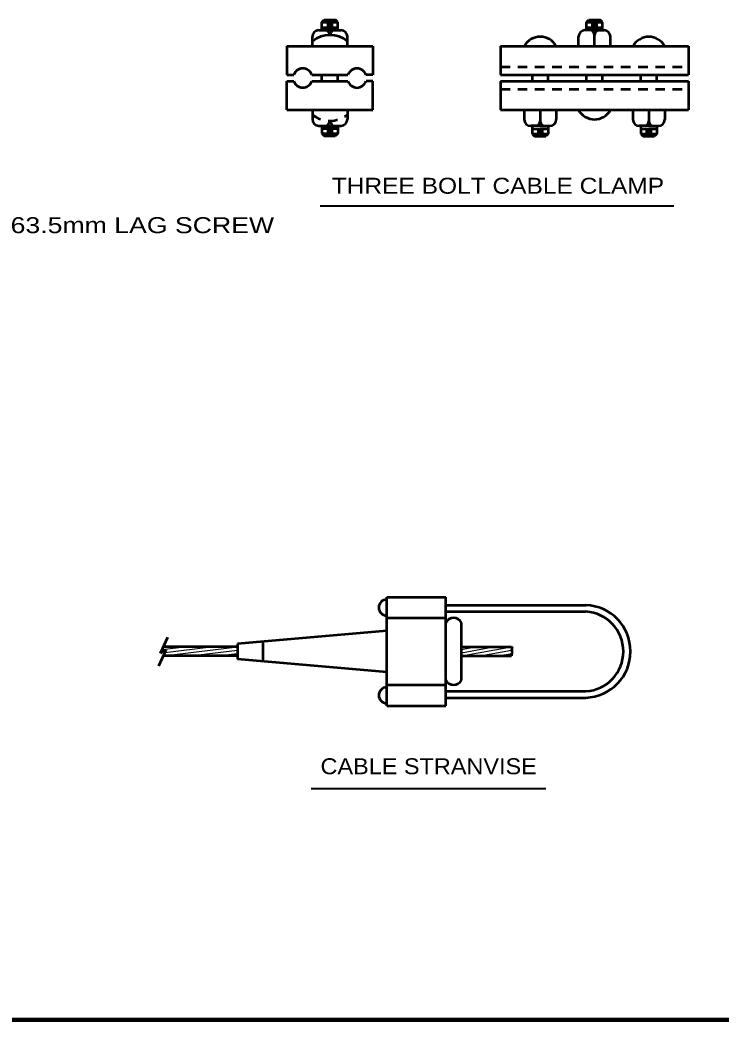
# Model space of a CAD drawing. Extents: x 14808 to 15663, y 10944 to 11488.
# Drawn here: x 15163.9 to 15295.9, y 10955.6 to 11143.7 of the extents above; entities that cross this region are included whole.
import ezdxf
from ezdxf.enums import TextEntityAlignment as Align

# ---------------------------------------------------------------- set-up
doc = ezdxf.new("R2010")
doc.units = 0
doc.header["$LTSCALE"] = 1.2
doc.linetypes.add('SHORT_DASHED', pattern=[2.7, 1.5, -1.2])
doc.layers.add('1', color=7, linetype='Continuous', lineweight=53)

msp = doc.modelspace()

# ---------------------------------------------------------------- linework, layer by layer
at = {"layer": '1'}
for p, q in [((15220.789, 11143.284), (15221.213, 11143.708)), ((15220.789, 11143.284), (15223.789, 11143.284)), ((15220.789, 11141.784), (15220.789, 11143.284)), ((15221.213, 11143.708), (15223.364, 11143.708)), ((15223.789, 11143.284), (15223.364, 11143.708)), ((15223.789, 11141.784), (15223.789, 11143.284)), ((15270.588, 11143.284), (15271.013, 11143.708)), ((15270.588, 11141.784), (15270.588, 11143.284)), ((15270.588, 11143.284), (15273.588, 11143.284)), ((15271.013, 11143.708), (15273.164, 11143.708)), ((15273.588, 11143.284), (15273.164, 11143.708)), ((15273.588, 11141.784), (15273.588, 11143.284)), ((15220.189, 11141.784), (15224.389, 11141.784)), ((15220.789, 11142.324), (15223.789, 11142.324)), ((15221.689, 11142.804), (15222.889, 11142.804)), ((15272.088, 11141.784), (15270.289, 11141.784)), ((15270.588, 11142.324), (15273.588, 11142.324)), ((15271.489, 11142.804), (15272.689, 11142.804)), ((15272.088, 11141.784), (15273.889, 11141.784)), ((15218.989, 11138.784), (15218.989, 11140.584)), ((15225.588, 11138.784), (15225.588, 11140.584)), ((15269.088, 11138.784), (15269.088, 11140.584)), ((15272.088, 11138.784), (15272.088, 11140.884)), ((15275.088, 11138.784), (15275.088, 11140.584)), ((15214.189, 11138.784), (15230.389, 11138.784)), ((15214.189, 11138.784), (15214.189, 11133.384)), ((15230.389, 11138.784), (15230.389, 11133.384)), ((15254.389, 11138.784), (15289.789, 11138.784)), ((15254.389, 11138.784), (15254.389, 11133.384)), ((15289.789, 11138.784), (15289.789, 11133.384)), ((15214.189, 11133.384), (15215.486, 11133.384)), ((15214.189, 11126.784), (15214.189, 11132.184)), ((15214.189, 11132.184), (15215.486, 11132.184)), ((15218.88, 11133.384), (15225.684, 11133.384)), ((15218.88, 11132.184), (15225.681, 11132.184)), ((15220.789, 11132.184), (15220.789, 11133.384)), ((15223.789, 11132.184), (15223.789, 11133.384)), ((15230.389, 11133.384), (15229.075, 11133.384)), ((15230.389, 11132.184), (15229.078, 11132.184)), ((15230.389, 11126.784), (15230.389, 11132.184)), ((15254.389, 11133.384), (15289.789, 11133.384)), ((15254.389, 11132.184), (15254.389, 11126.784)), ((15260.389, 11132.184), (15260.389, 11133.384)), ((15263.389, 11132.184), (15263.389, 11133.384)), ((15270.588, 11132.184), (15270.588, 11133.384)), ((15273.588, 11132.184), (15273.588, 11133.384)), ((15280.789, 11132.184), (15280.789, 11133.384)), ((15283.789, 11132.184), (15283.789, 11133.384)), ((15289.789, 11132.184), (15289.789, 11126.784)), ((15214.189, 11126.784), (15230.389, 11126.784)), ((15218.989, 11126.833), (15218.989, 11125.033)), ((15225.588, 11126.833), (15225.588, 11125.033)), ((15254.389, 11126.784), (15289.789, 11126.784)), ((15258.872, 11126.792), (15258.872, 11124.992)), ((15261.872, 11126.792), (15261.872, 11124.692)), ((15264.872, 11126.792), (15264.872, 11124.992)), ((15279.311, 11126.779), (15279.311, 11124.979)), ((15282.311, 11126.779), (15282.311, 11124.679)), ((15285.311, 11126.779), (15285.311, 11124.979)), ((15220.189, 11123.833), (15224.389, 11123.833)), ((15220.789, 11123.833), (15220.789, 11122.333)), ((15220.789, 11123.293), (15223.789, 11123.293)), ((15221.689, 11122.813), (15222.889, 11122.813)), ((15223.789, 11123.833), (15223.789, 11122.333)), ((15261.872, 11123.792), (15260.072, 11123.792)), ((15260.372, 11123.792), (15260.372, 11122.292)), ((15260.372, 11123.252), (15263.372, 11123.252)), ((15261.272, 11122.772), (15262.472, 11122.772)), ((15261.872, 11123.792), (15263.672, 11123.792)), ((15263.372, 11123.792), (15263.372, 11122.292)), ((15282.311, 11123.779), (15280.511, 11123.779)), ((15280.811, 11123.779), (15280.811, 11122.279)), ((15280.811, 11123.239), (15283.811, 11123.239)), ((15281.711, 11122.759), (15282.911, 11122.759)), ((15282.311, 11123.779), (15284.111, 11123.779)), ((15283.811, 11123.779), (15283.811, 11122.279)), ((15220.789, 11122.333), (15221.213, 11121.909)), ((15220.789, 11122.333), (15223.789, 11122.333)), ((15221.213, 11121.909), (15223.364, 11121.909)), ((15223.789, 11122.333), (15223.364, 11121.909)), ((15260.372, 11122.292), (15260.796, 11121.868)), ((15260.372, 11122.292), (15263.372, 11122.292)), ((15260.796, 11121.868), (15262.948, 11121.868)), ((15263.372, 11122.292), (15262.948, 11121.868)), ((15280.811, 11122.279), (15281.235, 11121.855)), ((15280.811, 11122.279), (15283.811, 11122.279)), ((15281.235, 11121.855), (15283.387, 11121.855)), ((15283.811, 11122.279), (15283.387, 11121.855)), ((15232.974, 11035.153), (15244.074, 11035.153)), ((15232.974, 11031.253), (15232.974, 11035.153)), ((15244.074, 11014.753), (15244.074, 11035.153)), ((15244.074, 11033.653), (15270.474, 11033.653)), ((15244.074, 11032.453), (15270.474, 11032.453)), ((15232.974, 11031.253), (15244.074, 11031.253)), ((15247.074, 11019.553), (15247.074, 11030.353)), ((15232.974, 11028.853), (15204.882, 11026.395)), ((15190.411, 11024.637), (15191.805, 11027.627)), ((15209.682, 11026.815), (15209.682, 11023.091)), ((15190.099, 11022.257), (15191.494, 11025.248)), ((15190.411, 11024.637), (15191.494, 11025.248)), ((15204.882, 11025.795), (15190.951, 11025.795)), ((15204.882, 11026.395), (15204.882, 11023.511)), ((15247.074, 11025.795), (15256.482, 11025.795)), ((15204.882, 11024.111), (15190.963, 11024.111)), ((15232.974, 11021.053), (15204.882, 11023.511)), ((15247.074, 11024.111), (15256.482, 11024.111)), ((15232.974, 11018.653), (15244.074, 11018.653)), ((15244.074, 11017.453), (15270.474, 11017.453)), ((15244.074, 11016.253), (15270.474, 11016.253)), ((15232.974, 11014.753), (15244.074, 11014.753))]:
    msp.add_line(p, q, dxfattribs=at)
at = {"layer": '1', "linetype": 'SHORT_DASHED'}
for p, q in [((15254.389, 11134.884), (15289.789, 11134.884)), ((15254.389, 11130.684), (15289.789, 11130.684))]:
    msp.add_line(p, q, dxfattribs=at)
at = {"layer": '1', "lineweight": 13}
msp.add_line((15218.889, 11133.384), (15218.989, 11133.384), dxfattribs=at)
at = {"layer": '1', "lineweight": 40}
for p, q in [((15220.426, 11108.781), (15286.991, 11108.781)), ((15218.777, 10999.203), (15262.909, 10999.203))]:
    msp.add_line(p, q, dxfattribs=at)
at = {"layer": '1', "lineweight": 25}
for p, q in [((15190.715, 11025.29), (15194.894, 11025.795)), ((15190.963, 11024.111), (15204.882, 11025.795)), ((15191.262, 11024.752), (15199.887, 11025.795)), ((15195.958, 11024.111), (15204.882, 11025.191)), ((15200.951, 11024.111), (15204.882, 11024.587)), ((15247.074, 11024.111), (15256.482, 11025.795)), ((15247.074, 11025.33), (15249.673, 11025.795)), ((15247.074, 11024.72), (15253.077, 11025.795)), ((15250.479, 11024.111), (15256.465, 11025.183)), ((15253.883, 11024.111), (15256.569, 11024.592))]:
    msp.add_line(p, q, dxfattribs=at)
at = {"layer": '1', "lineweight": 158}
msp.add_line((15656.868, 10955.64), (14865.268, 10955.64), dxfattribs=at)
at = {"layer": '1'}
for points in [[(15254.389, 11132.184), (15260.389, 11132.184), (15263.389, 11132.184), (15280.789, 11132.184)], [(15280.789, 11132.184), (15283.789, 11132.184), (15289.789, 11132.184)], [(15232.974, 11014.753), (15232.974, 11018.653), (15232.974, 11031.253)]]:
    msp.add_lwpolyline(points, dxfattribs=at)
for centre, radius, start, end in [((15220.189, 11140.584), 1.2, 90, 180), ((15220.696, 11140.472), 1.645, 14.49718, 52.88295), ((15223.873, 11140.472), 1.645, 127.11705, 165.50282), ((15224.389, 11140.584), 1.2, 0, 90), ((15270.289, 11140.584), 1.2, 90, 180), ((15271.032, 11140.83), 1.058, 2.94427, 64.43586), ((15273.145, 11140.83), 1.058, 115.56414, 177.05572), ((15273.889, 11140.584), 1.2, 0, 90), ((15222.289, 11135.746), 5.138, 50.03379, 129.96621), ((15261.872, 11137.12), 3.435, 29.14172, 150.85828), ((15282.311, 11137.107), 3.435, 29.14172, 150.85828), ((15217.183, 11132.783), 1.8, 19.49795, 160.50177), ((15227.379, 11132.78), 1.8, 19.58943, 160.41041), ((15217.183, 11132.783), 1.8, 199.44421, 340.55538), ((15227.379, 11132.78), 1.8, 199.35299, 340.6469), ((15272.088, 11128.457), 3.435, 209.14172, 330.85828), ((15220.189, 11125.033), 1.2, 180, 270), ((15220.696, 11125.145), 1.645, 307.11705, 345.50282), ((15223.873, 11125.145), 1.645, 194.49718, 232.88295), ((15224.389, 11125.033), 1.2, 270, 0), ((15260.072, 11124.992), 1.2, 180, 270), ((15260.815, 11124.747), 1.058, 295.56414, 357.05572), ((15262.928, 11124.747), 1.058, 182.94428, 244.43586), ((15263.672, 11124.992), 1.2, 270, 0), ((15280.511, 11124.979), 1.2, 180, 270), ((15281.254, 11124.734), 1.058, 295.56414, 357.05572), ((15283.368, 11124.734), 1.058, 182.94428, 244.43586), ((15284.111, 11124.979), 1.2, 270, 0), ((15232.974, 11033.203), 1.5, 90, 270), ((15270.169, 11024.953), 8.705, 272.01017, 87.98983), ((15270.003, 11024.953), 7.515, 273.59778, 86.40223), ((15245.574, 11029.553), 1.7, 28.07249, 151.92751), ((15245.574, 11020.352), 1.7, 208.07249, 331.92751), ((15232.974, 11016.703), 1.5, 90, 270)]:
    msp.add_arc(centre, radius, start, end, dxfattribs=at)
at = {"layer": '1', "lineweight": 13}
msp.add_arc((15217.183, 11132.783), 1.8, 199.26221, 340.15338, dxfattribs=at)
at = {"layer": '1', "linetype": 'SHORT_DASHED'}
msp.add_arc((15222.289, 11129.871), 5.138, 230.03379, 309.96621, dxfattribs=at)
at = {"layer": '1'}
msp.add_spline([(15256.482, 11025.795), (15256.581, 11025.634), (15256.504, 11025.519), (15256.53, 11025.339), (15256.466, 11025.185), (15256.568, 11025.057), (15256.517, 11024.942), (15256.556, 11024.724), (15256.543, 11024.545), (15256.466, 11024.404), (15256.479, 11024.327), (15256.482, 11024.111)], degree=3, dxfattribs=at)

# ---------------------------------------------------------------- texts
for s, width, p in [('THREE BOLT CABLE CLAMP', 1.15, (15253.911, 11111.036)), ('CABLE STRANVISE', 1.1, (15240.875, 11001.861))]:
    msp.add_text(s, height=3, dxfattribs=dict(at, width=width)).set_placement(p, align=Align.CENTER)
at = {"layer": '1', "width": 1.25}
msp.add_text('9.525mmx63.5mm LAG SCREW', height=3, dxfattribs=at).set_placement((15138.771, 11103.619))

doc.saveas('drawing.dxf')
